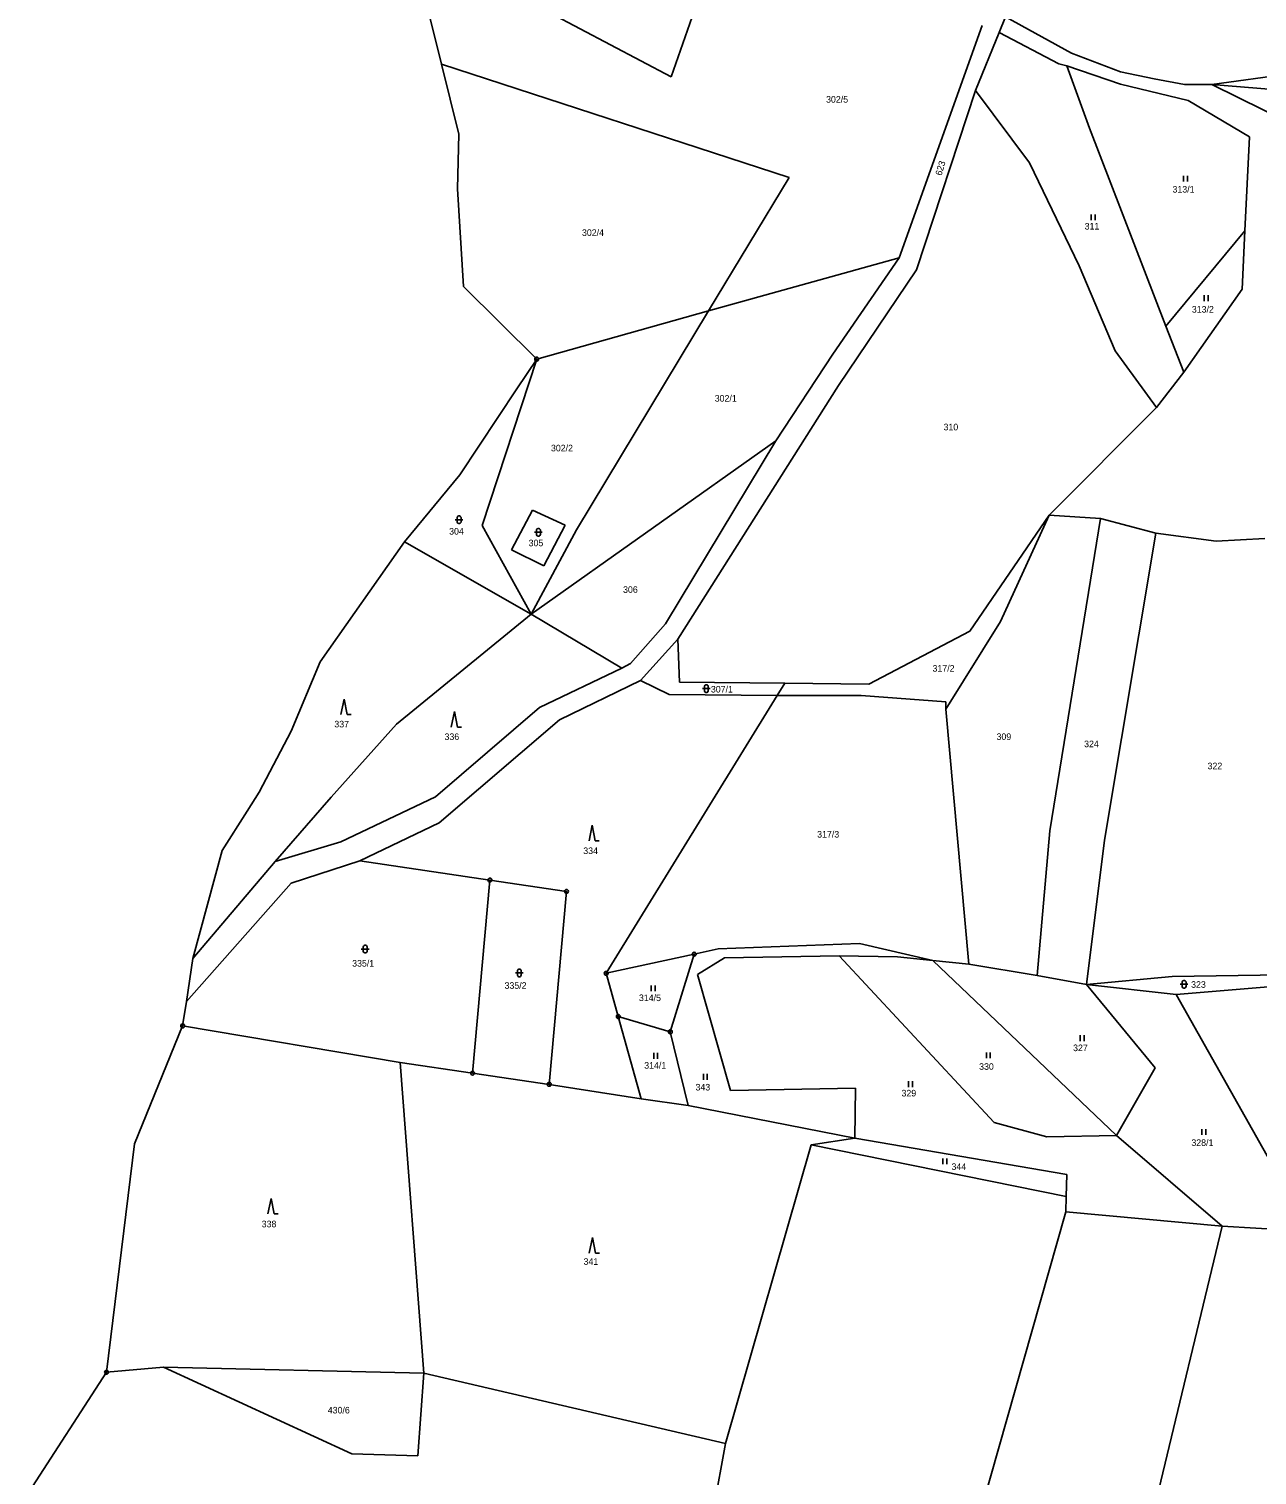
# Model space of a CAD drawing. Extents: x -794421 to -792735, y -1117671 to -1115559.
# Drawn here: x -794340.9 to -794023.8, y -1116790.7 to -1116417 of the extents above; entities that cross this region are included whole.
import ezdxf

# ---------------------------------------------------------------- set-up
doc = ezdxf.new("R2010")
doc.units = 0
for name, color, linetype in [('Vrstva 1', 7, 'Continuous'), ('Vrstva 14', 7, 'Continuous'), ('Vrstva 23', 7, 'Continuous'), ('Vrstva 28', 7, 'Continuous'), ('Vrstva 4', 7, 'Continuous')]:
    doc.layers.add(name, color=color, linetype=linetype)

msp = doc.modelspace()

# ---------------------------------------------------------------- linework, layer by layer
at = {"layer": 'Vrstva 1'}
for p, q in [((-794244.57, -1116392.62), (-794175.05, -1116429.4)), ((-794175.05, -1116429.4), (-794162.06, -1116392.12)), ((-794116.23, -1116476.12), (-794094.72, -1116416.1)), ((-794090.34, -1116417.91), (-794088.71, -1116413.91)), ((-794088.71, -1116413.91), (-794071.7, -1116423.26)), ((-794096.48, -1116432.92), (-794090.34, -1116417.91)), ((-794074.93, -1116426.06), (-794090.34, -1116417.91)), ((-794071.7, -1116423.26), (-794058.99, -1116428.1)), ((-794234.41, -1116426.14), (-794144.6, -1116455.4)), ((-794072.86, -1116426.56), (-794074.93, -1116426.06)), ((-794067.05, -1116442.62), (-794072.86, -1116426.56)), ((-794059.04, -1116431.26), (-794072.86, -1116426.56)), ((-794058.99, -1116428.1), (-794050.36, -1116429.88)), ((-794035.4, -1116431.36), (-794001.78, -1116426.7)), ((-794059.04, -1116431.26), (-794041.54, -1116435.54)), ((-794050.36, -1116429.88), (-794042.5, -1116431.36)), ((-794042.5, -1116431.36), (-794035.4, -1116431.36)), ((-794035.4, -1116431.36), (-793998.97, -1116434.36)), ((-794035.4, -1116431.36), (-793992.19, -1116452.85)), ((-794111.72, -1116479.23), (-794096.48, -1116432.92)), ((-794096.48, -1116432.92), (-794082.49, -1116451.61)), ((-794041.54, -1116435.54), (-794025.75, -1116444.93)), ((-794067.05, -1116442.62), (-794047.28, -1116493.82)), ((-794025.75, -1116444.93), (-794026.91, -1116469.16)), ((-794082.49, -1116451.61), (-794069.66, -1116478.2)), ((-794144.6, -1116455.4), (-794165.39, -1116489.89)), ((-794047.28, -1116493.82), (-794026.91, -1116469.16)), ((-794026.91, -1116469.16), (-794027.63, -1116484.27)), ((-794165.39, -1116489.89), (-794116.23, -1116476.12)), ((-794133.36, -1116501.05), (-794116.23, -1116476.12)), ((-794131.89, -1116509.17), (-794111.72, -1116479.23)), ((-794069.66, -1116478.2), (-794060.4, -1116500.22)), ((-794027.63, -1116484.27), (-794042.7, -1116505.69)), ((-794209.8, -1116502.32), (-794165.39, -1116489.89)), ((-794165.39, -1116489.89), (-794199.51, -1116546.48)), ((-794047.28, -1116493.82), (-794042.7, -1116505.69)), ((-794209.8, -1116502.32), (-794223.9, -1116545.32)), ((-794148.01, -1116523.41), (-794133.36, -1116501.05)), ((-794060.4, -1116500.22), (-794049.74, -1116514.82)), ((-794049.74, -1116514.82), (-794042.7, -1116505.69)), ((-794173.31, -1116574.7), (-794131.89, -1116509.17)), ((-794049.74, -1116514.82), (-794077.49, -1116542.67)), ((-794211.23, -1116568.23), (-794148.01, -1116523.41)), ((-794176.57, -1116570.74), (-794148.01, -1116523.41)), ((-794216.27, -1116551.59), (-794210.85, -1116541.4)), ((-794210.85, -1116541.4), (-794202.43, -1116545.21)), ((-794097.95, -1116572.63), (-794077.49, -1116542.67)), ((-794077.49, -1116542.67), (-794089.98, -1116570.16)), ((-794077.49, -1116542.67), (-794064.16, -1116543.49)), ((-794064.16, -1116543.49), (-794077.32, -1116624.19)), ((-794064.16, -1116543.49), (-794049.89, -1116547.29)), ((-794223.9, -1116545.32), (-794211.23, -1116568.23)), ((-794199.51, -1116546.48), (-794211.23, -1116568.23)), ((-794202.43, -1116545.21), (-794207.99, -1116555.75)), ((-794063.2, -1116626.64), (-794049.89, -1116547.29)), ((-794049.89, -1116547.29), (-794034.33, -1116549.35)), ((-794211.23, -1116568.23), (-794243.97, -1116549.55)), ((-794034.33, -1116549.35), (-794021.77, -1116548.68)), ((-794207.99, -1116555.75), (-794216.27, -1116551.59)), ((-794246.04, -1116596.68), (-794211.23, -1116568.23)), ((-794211.23, -1116568.23), (-794187.83, -1116582.17)), ((-794089.98, -1116570.16), (-794104.11, -1116592.76)), ((-794185.61, -1116581.02), (-794176.57, -1116570.74)), ((-794124.01, -1116586.29), (-794097.95, -1116572.63)), ((-794182.96, -1116585.39), (-794173.31, -1116574.7)), ((-794173.31, -1116574.7), (-794172.91, -1116585.83)), ((-794187.83, -1116582.17), (-794185.61, -1116581.02)), ((-794187.83, -1116582.17), (-794209.07, -1116592.34)), ((-794203.88, -1116595.52), (-794182.96, -1116585.39)), ((-794182.96, -1116585.39), (-794175.55, -1116588.96)), ((-794172.91, -1116585.83), (-794145.69, -1116586.05)), ((-794145.69, -1116586.05), (-794147.71, -1116589.22)), ((-794145.69, -1116586.05), (-794124.01, -1116586.29)), ((-794209.07, -1116592.34), (-794235.95, -1116615.48)), ((-794147.71, -1116589.22), (-794191.85, -1116661.04)), ((-794175.55, -1116588.96), (-794147.71, -1116589.22)), ((-794125.97, -1116589.25), (-794147.71, -1116589.22)), ((-794104.11, -1116590.86), (-794125.97, -1116589.25)), ((-794104.11, -1116592.76), (-794104.11, -1116590.86)), ((-794234.99, -1116622.17), (-794203.88, -1116595.52)), ((-794104.11, -1116592.76), (-794098.19, -1116658.64)), ((-794262.9, -1116615.5), (-794246.04, -1116596.68)), ((-794277.37, -1116632.14), (-794262.9, -1116615.5)), ((-794235.95, -1116615.48), (-794260.42, -1116627.06)), ((-794255.48, -1116631.96), (-794234.99, -1116622.17)), ((-794080.56, -1116661.58), (-794077.32, -1116624.19)), ((-794260.42, -1116627.06), (-794277.37, -1116632.14)), ((-794067.83, -1116663.94), (-794063.2, -1116626.64)), ((-794277.37, -1116632.14), (-794298.6, -1116657.2)), ((-794255.48, -1116631.96), (-794273.25, -1116637.79)), ((-794221.88, -1116636.94), (-794255.48, -1116631.96)), ((-794226.35, -1116686.85), (-794221.88, -1116636.94)), ((-794221.88, -1116636.94), (-794202.1, -1116639.87)), ((-794273.25, -1116637.79), (-794300.27, -1116668.31)), ((-794202.1, -1116639.87), (-794206.56, -1116689.74)), ((-794191.85, -1116661.04), (-794169.1, -1116656.09)), ((-794169.1, -1116656.09), (-794175.29, -1116676.15)), ((-794169.1, -1116656.09), (-794162.97, -1116654.75)), ((-794162.97, -1116654.75), (-794126.4, -1116653.35)), ((-794126.4, -1116653.35), (-794107.52, -1116657.75)), ((-794161.33, -1116657.03), (-794168.23, -1116661.37)), ((-794131.7, -1116656.53), (-794161.33, -1116657.03)), ((-794091.62, -1116699.56), (-794131.7, -1116656.53)), ((-794131.7, -1116656.53), (-794116.59, -1116656.76)), ((-794116.59, -1116656.76), (-794107.52, -1116657.75)), ((-794107.52, -1116657.75), (-794098.19, -1116658.64)), ((-794107.52, -1116657.75), (-794060.09, -1116702.91)), ((-794098.19, -1116658.64), (-794080.56, -1116661.58)), ((-794188.73, -1116672.22), (-794191.85, -1116661.04)), ((-794168.23, -1116661.37), (-794159.73, -1116691.31)), ((-794080.56, -1116661.58), (-794067.83, -1116663.94)), ((-794067.83, -1116663.94), (-794045.68, -1116661.89)), ((-794045.68, -1116661.89), (-794017.25, -1116661.45)), ((-794050.08, -1116685.51), (-794067.83, -1116663.94)), ((-794044.65, -1116666.54), (-794067.83, -1116663.94)), ((-794017.78, -1116664.26), (-794044.65, -1116666.54)), ((-794016.55, -1116716.31), (-794044.65, -1116666.54)), ((-794301.23, -1116674.64), (-794245.1, -1116684.12)), ((-794175.29, -1116676.15), (-794188.73, -1116672.22)), ((-794182.8, -1116693.45), (-794188.73, -1116672.22)), ((-794175.29, -1116676.15), (-794170.66, -1116695.21)), ((-794238.94, -1116764.35), (-794245.1, -1116684.12)), ((-794245.1, -1116684.12), (-794226.35, -1116686.85)), ((-794060.09, -1116702.91), (-794050.08, -1116685.51)), ((-794226.35, -1116686.85), (-794206.56, -1116689.74)), ((-794206.56, -1116689.74), (-794182.8, -1116693.45)), ((-794182.8, -1116693.45), (-794170.66, -1116695.21)), ((-794159.73, -1116691.31), (-794127.45, -1116690.76)), ((-794127.45, -1116690.76), (-794127.65, -1116703.6)), ((-794127.65, -1116703.6), (-794170.66, -1116695.21)), ((-794078.09, -1116703.28), (-794091.62, -1116699.56)), ((-794138.88, -1116705.38), (-794127.65, -1116703.6)), ((-794127.65, -1116703.6), (-794072.87, -1116713)), ((-794060.09, -1116702.91), (-794078.09, -1116703.28)), ((-794060.09, -1116702.91), (-794032.73, -1116726.38)), ((-794138.88, -1116705.38), (-794161.02, -1116782.51)), ((-794073.04, -1116718.68), (-794138.88, -1116705.38)), ((-794072.87, -1116713), (-794073.04, -1116718.68)), ((-794073.14, -1116722.69), (-794073.04, -1116718.68)), ((-794100.53, -1116819.2), (-794073.14, -1116722.69)), ((-794032.73, -1116726.38), (-794073.14, -1116722.69)), ((-794032.73, -1116726.38), (-794063.93, -1116855.67)), ((-793993.84, -1116728.72), (-794032.73, -1116726.38)), ((-794306.17, -1116762.81), (-794320.91, -1116764.13)), ((-794306.17, -1116762.81), (-794257.58, -1116785.23)), ((-794238.94, -1116764.35), (-794306.17, -1116762.81)), ((-794240.5, -1116785.74), (-794238.94, -1116764.35)), ((-794161.02, -1116782.51), (-794238.94, -1116764.35)), ((-794161.02, -1116782.51), (-794170.01, -1116832.22)), ((-794257.58, -1116785.23), (-794240.5, -1116785.74))]:
    msp.add_line(p, q, dxfattribs=at)
at = {"layer": 'Vrstva 23'}
for p, q in [((-794042.76, -1116456.46), (-794042.76, -1116454.96)), ((-794041.76, -1116454.96), (-794041.76, -1116456.46)), ((-794066.6, -1116466.45), (-794066.6, -1116464.95)), ((-794065.6, -1116464.95), (-794065.6, -1116466.45)), ((-794037.4, -1116487.33), (-794037.4, -1116485.83)), ((-794036.4, -1116485.83), (-794036.4, -1116487.33)), ((-794230.84, -1116543.85), (-794228.84, -1116543.85)), ((-794230.34, -1116543.25), (-794230.24, -1116543.05)), ((-794230.34, -1116544.45), (-794230.34, -1116543.25)), ((-794230.24, -1116543.05), (-794230.14, -1116542.95)), ((-794230.14, -1116542.95), (-794229.94, -1116542.85)), ((-794229.94, -1116542.85), (-794229.74, -1116542.85)), ((-794229.74, -1116542.85), (-794229.54, -1116542.95)), ((-794229.54, -1116542.95), (-794229.44, -1116543.05)), ((-794229.44, -1116543.05), (-794229.34, -1116543.25)), ((-794229.34, -1116543.25), (-794229.34, -1116544.45)), ((-794230.24, -1116544.65), (-794230.34, -1116544.45)), ((-794230.14, -1116544.75), (-794230.24, -1116544.65)), ((-794229.94, -1116544.85), (-794230.14, -1116544.75)), ((-794229.74, -1116544.85), (-794229.94, -1116544.85)), ((-794229.54, -1116544.75), (-794229.74, -1116544.85)), ((-794229.44, -1116544.65), (-794229.54, -1116544.75)), ((-794229.34, -1116544.45), (-794229.44, -1116544.65)), ((-794210.35, -1116547.07), (-794208.35, -1116547.07)), ((-794209.85, -1116546.47), (-794209.75, -1116546.27)), ((-794209.85, -1116547.67), (-794209.85, -1116546.47)), ((-794209.75, -1116547.87), (-794209.85, -1116547.67)), ((-794209.75, -1116546.27), (-794209.65, -1116546.17)), ((-794209.65, -1116546.17), (-794209.45, -1116546.07)), ((-794209.45, -1116546.07), (-794209.25, -1116546.07)), ((-794209.25, -1116546.07), (-794209.05, -1116546.17)), ((-794209.05, -1116546.17), (-794208.95, -1116546.27)), ((-794208.95, -1116546.27), (-794208.85, -1116546.47)), ((-794208.85, -1116547.67), (-794208.95, -1116547.87)), ((-794208.85, -1116546.47), (-794208.85, -1116547.67)), ((-794209.65, -1116547.97), (-794209.75, -1116547.87)), ((-794209.45, -1116548.07), (-794209.65, -1116547.97)), ((-794209.25, -1116548.07), (-794209.45, -1116548.07)), ((-794209.05, -1116547.97), (-794209.25, -1116548.07)), ((-794208.95, -1116547.87), (-794209.05, -1116547.97)), ((-794166.99, -1116587.48), (-794164.99, -1116587.48)), ((-794166.49, -1116586.88), (-794166.39, -1116586.68)), ((-794166.49, -1116588.08), (-794166.49, -1116586.88)), ((-794166.39, -1116588.28), (-794166.49, -1116588.08)), ((-794166.39, -1116586.68), (-794166.29, -1116586.58)), ((-794166.29, -1116588.38), (-794166.39, -1116588.28)), ((-794166.29, -1116586.58), (-794166.09, -1116586.48)), ((-794166.09, -1116588.48), (-794166.29, -1116588.38)), ((-794166.09, -1116586.48), (-794165.89, -1116586.48)), ((-794165.89, -1116588.48), (-794166.09, -1116588.48)), ((-794165.89, -1116586.48), (-794165.69, -1116586.58)), ((-794165.69, -1116588.38), (-794165.89, -1116588.48)), ((-794165.69, -1116586.58), (-794165.59, -1116586.68)), ((-794165.59, -1116588.28), (-794165.69, -1116588.38)), ((-794165.59, -1116586.68), (-794165.49, -1116586.88)), ((-794165.49, -1116588.08), (-794165.59, -1116588.28)), ((-794165.49, -1116586.88), (-794165.49, -1116588.08)), ((-794260.35, -1116594.2), (-794259.55, -1116590.2)), ((-794259.55, -1116590.2), (-794258.75, -1116594.2)), ((-794258.75, -1116594.2), (-794257.75, -1116594.2)), ((-794231.86, -1116597.42), (-794231.06, -1116593.42)), ((-794231.06, -1116593.42), (-794230.26, -1116597.42)), ((-794230.26, -1116597.42), (-794229.26, -1116597.42)), ((-794196.28, -1116626.77), (-794195.48, -1116622.77)), ((-794195.48, -1116622.77), (-794194.68, -1116626.77)), ((-794194.68, -1116626.77), (-794193.68, -1116626.77)), ((-794255.09, -1116654.79), (-794253.09, -1116654.79)), ((-794254.59, -1116654.19), (-794254.49, -1116653.99)), ((-794254.59, -1116655.39), (-794254.59, -1116654.19)), ((-794254.49, -1116655.59), (-794254.59, -1116655.39)), ((-794254.49, -1116653.99), (-794254.39, -1116653.89)), ((-794254.39, -1116655.69), (-794254.49, -1116655.59)), ((-794254.39, -1116653.89), (-794254.19, -1116653.79)), ((-794254.19, -1116655.79), (-794254.39, -1116655.69)), ((-794254.19, -1116653.79), (-794253.99, -1116653.79)), ((-794253.99, -1116655.79), (-794254.19, -1116655.79)), ((-794253.99, -1116653.79), (-794253.79, -1116653.89)), ((-794253.79, -1116655.69), (-794253.99, -1116655.79)), ((-794253.79, -1116653.89), (-794253.69, -1116653.99)), ((-794253.69, -1116655.59), (-794253.79, -1116655.69)), ((-794253.69, -1116653.99), (-794253.59, -1116654.19)), ((-794253.59, -1116655.39), (-794253.69, -1116655.59)), ((-794253.59, -1116654.19), (-794253.59, -1116655.39)), ((-794214.59, -1116660.03), (-794214.39, -1116659.93)), ((-794214.39, -1116659.93), (-794214.19, -1116659.93)), ((-794214.19, -1116659.93), (-794213.99, -1116660.03)), ((-794215.29, -1116660.93), (-794213.29, -1116660.93)), ((-794214.79, -1116660.33), (-794214.69, -1116660.13)), ((-794214.79, -1116661.53), (-794214.79, -1116660.33)), ((-794214.69, -1116661.73), (-794214.79, -1116661.53)), ((-794214.69, -1116660.13), (-794214.59, -1116660.03)), ((-794214.59, -1116661.83), (-794214.69, -1116661.73)), ((-794214.39, -1116661.93), (-794214.59, -1116661.83)), ((-794214.19, -1116661.93), (-794214.39, -1116661.93)), ((-794213.99, -1116661.83), (-794214.19, -1116661.93)), ((-794213.99, -1116660.03), (-794213.89, -1116660.13)), ((-794213.89, -1116661.73), (-794213.99, -1116661.83)), ((-794213.89, -1116660.13), (-794213.79, -1116660.33)), ((-794213.79, -1116661.53), (-794213.89, -1116661.73)), ((-794213.79, -1116660.33), (-794213.79, -1116661.53)), ((-794043.1, -1116663.27), (-794043, -1116663.07)), ((-794043.1, -1116664.47), (-794043.1, -1116663.27)), ((-794043, -1116663.07), (-794042.9, -1116662.97)), ((-794042.9, -1116662.97), (-794042.7, -1116662.87)), ((-794042.7, -1116662.87), (-794042.5, -1116662.87)), ((-794042.5, -1116662.87), (-794042.3, -1116662.97)), ((-794042.3, -1116662.97), (-794042.2, -1116663.07)), ((-794042.2, -1116663.07), (-794042.1, -1116663.27)), ((-794042.1, -1116663.27), (-794042.1, -1116664.47)), ((-794180.23, -1116665.67), (-794180.23, -1116664.17)), ((-794179.23, -1116664.17), (-794179.23, -1116665.67)), ((-794043.6, -1116663.87), (-794041.6, -1116663.87)), ((-794043, -1116664.67), (-794043.1, -1116664.47)), ((-794042.9, -1116664.77), (-794043, -1116664.67)), ((-794042.7, -1116664.87), (-794042.9, -1116664.77)), ((-794042.5, -1116664.87), (-794042.7, -1116664.87)), ((-794042.3, -1116664.77), (-794042.5, -1116664.87)), ((-794042.2, -1116664.67), (-794042.3, -1116664.77)), ((-794042.1, -1116664.47), (-794042.2, -1116664.67)), ((-794069.44, -1116678.54), (-794069.44, -1116677.04)), ((-794068.44, -1116677.04), (-794068.44, -1116678.54)), ((-794179.56, -1116683.11), (-794179.56, -1116681.61)), ((-794178.56, -1116681.61), (-794178.56, -1116683.11)), ((-794093.66, -1116683), (-794093.66, -1116681.5)), ((-794092.66, -1116681.5), (-794092.66, -1116683)), ((-794166.75, -1116688.56), (-794166.75, -1116687.06)), ((-794165.75, -1116687.06), (-794165.75, -1116688.56)), ((-794113.77, -1116690.45), (-794113.77, -1116688.95)), ((-794112.77, -1116688.95), (-794112.77, -1116690.45)), ((-794037.98, -1116702.82), (-794037.98, -1116701.32)), ((-794036.98, -1116701.32), (-794036.98, -1116702.82)), ((-794104.92, -1116710.38), (-794104.92, -1116708.88)), ((-794103.92, -1116708.88), (-794103.92, -1116710.38)), ((-794279.2, -1116723.2), (-794278.4, -1116719.2)), ((-794278.4, -1116719.2), (-794277.6, -1116723.2)), ((-794277.6, -1116723.2), (-794276.6, -1116723.2)), ((-794196.21, -1116733.35), (-794195.41, -1116729.35)), ((-794195.41, -1116729.35), (-794194.61, -1116733.35)), ((-794194.61, -1116733.35), (-794193.61, -1116733.35))]:
    msp.add_line(p, q, dxfattribs=at)
at = {"layer": 'Vrstva 28'}
for centre, radius in [((-794209.8, -1116502.32), 0.5), ((-794209.8, -1116502.32), 0.01), ((-794221.88, -1116636.94), 0.5), ((-794221.88, -1116636.94), 0.01), ((-794202.1, -1116639.87), 0.5), ((-794202.1, -1116639.87), 0.01), ((-794169.1, -1116656.09), 0.5), ((-794169.1, -1116656.09), 0.01), ((-794191.85, -1116661.04), 0.5), ((-794191.85, -1116661.04), 0.01), ((-794301.23, -1116674.64), 0.5), ((-794301.23, -1116674.64), 0.01), ((-794188.73, -1116672.22), 0.5), ((-794188.73, -1116672.22), 0.01), ((-794175.29, -1116676.15), 0.5), ((-794175.29, -1116676.15), 0.01), ((-794226.35, -1116686.85), 0.5), ((-794226.35, -1116686.85), 0.01), ((-794206.56, -1116689.74), 0.5), ((-794206.56, -1116689.74), 0.01), ((-794320.91, -1116764.13), 0.5), ((-794320.91, -1116764.13), 0.01)]:
    msp.add_circle(centre, radius, dxfattribs=at)
at = {"layer": 'Vrstva 4'}
for p, q in [((-794237.52, -1116413.58), (-794234.41, -1116426.14)), ((-794234.41, -1116426.14), (-794229.94, -1116444.22)), ((-794229.94, -1116444.22), (-794230.24, -1116458.33)), ((-794230.24, -1116458.33), (-794228.66, -1116483.56)), ((-794228.66, -1116483.56), (-794209.8, -1116502.32)), ((-794209.8, -1116502.32), (-794214.9, -1116509.98)), ((-794214.9, -1116509.98), (-794229.68, -1116532.2)), ((-794229.68, -1116532.2), (-794243.97, -1116549.55)), ((-794243.97, -1116549.55), (-794265.76, -1116580.56)), ((-794265.76, -1116580.56), (-794273.24, -1116598.47)), ((-794273.24, -1116598.47), (-794281.44, -1116614.2)), ((-794281.44, -1116614.2), (-794284.56, -1116619.14)), ((-794284.56, -1116619.14), (-794290.99, -1116629.32)), ((-794290.99, -1116629.32), (-794298.6, -1116657.2)), ((-794298.6, -1116657.2), (-794300.27, -1116668.31)), ((-794300.27, -1116668.31), (-794301.23, -1116674.64)), ((-794301.23, -1116674.64), (-794313.7, -1116705.11)), ((-794313.7, -1116705.11), (-794320.91, -1116764.13)), ((-794320.91, -1116764.13), (-794340.93, -1116795.12))]:
    msp.add_line(p, q, dxfattribs=at)

# ---------------------------------------------------------------- texts
at = {"layer": 'Vrstva 14'}
for s, p in [('302/5', (-794135.065, -1116436.06)), ('313/1', (-794045.596, -1116459.29)), ('302/4', (-794198.105, -1116470.49)), ('311', (-794068.293, -1116468.84)), ('313/2', (-794040.603, -1116490.31)), ('302/1', (-794163.822, -1116513.31)), ('310', (-794104.729, -1116520.73)), ('302/2', (-794206.119, -1116526.17)), ('304', (-794232.412, -1116547.67)), ('305', (-794211.892, -1116550.68)), ('306', (-794187.496, -1116562.73)), ('317/2', (-794107.58, -1116583.1)), ('307/1', (-794164.809, -1116588.48)), ('337', (-794262.063, -1116597.5)), ('336', (-794233.607, -1116600.76)), ('309', (-794091.046, -1116600.75)), ('324', (-794068.422, -1116602.61)), ('322', (-794036.546, -1116608.31)), ('317/3', (-794137.37, -1116625.96)), ('334', (-794197.773, -1116630.23)), ('335/1', (-794257.46, -1116659.31)), ('335/2', (-794218.106, -1116665.04)), ('323', (-794040.787, -1116664.78)), ('314/5', (-794183.395, -1116668.22)), ('327', (-794071.273, -1116681.15)), ('314/1', (-794182.032, -1116685.69)), ('330', (-794095.536, -1116685.98)), ('343', (-794168.783, -1116691.32)), ('329', (-794115.587, -1116692.86)), ('328/1', (-794040.723, -1116705.65)), ('344', (-794102.678, -1116711.86)), ('338', (-794280.817, -1116726.67)), ('341', (-794197.696, -1116736.38)), ('430/6', (-794263.755, -1116774.78))]:
    msp.add_text(s, height=1.7, dxfattribs=at).set_placement(p)
msp.add_text('623', height=1.7, rotation=73.41615, dxfattribs=at).set_placement((-794105.262, -1116455.034))

doc.saveas('drawing.dxf')
